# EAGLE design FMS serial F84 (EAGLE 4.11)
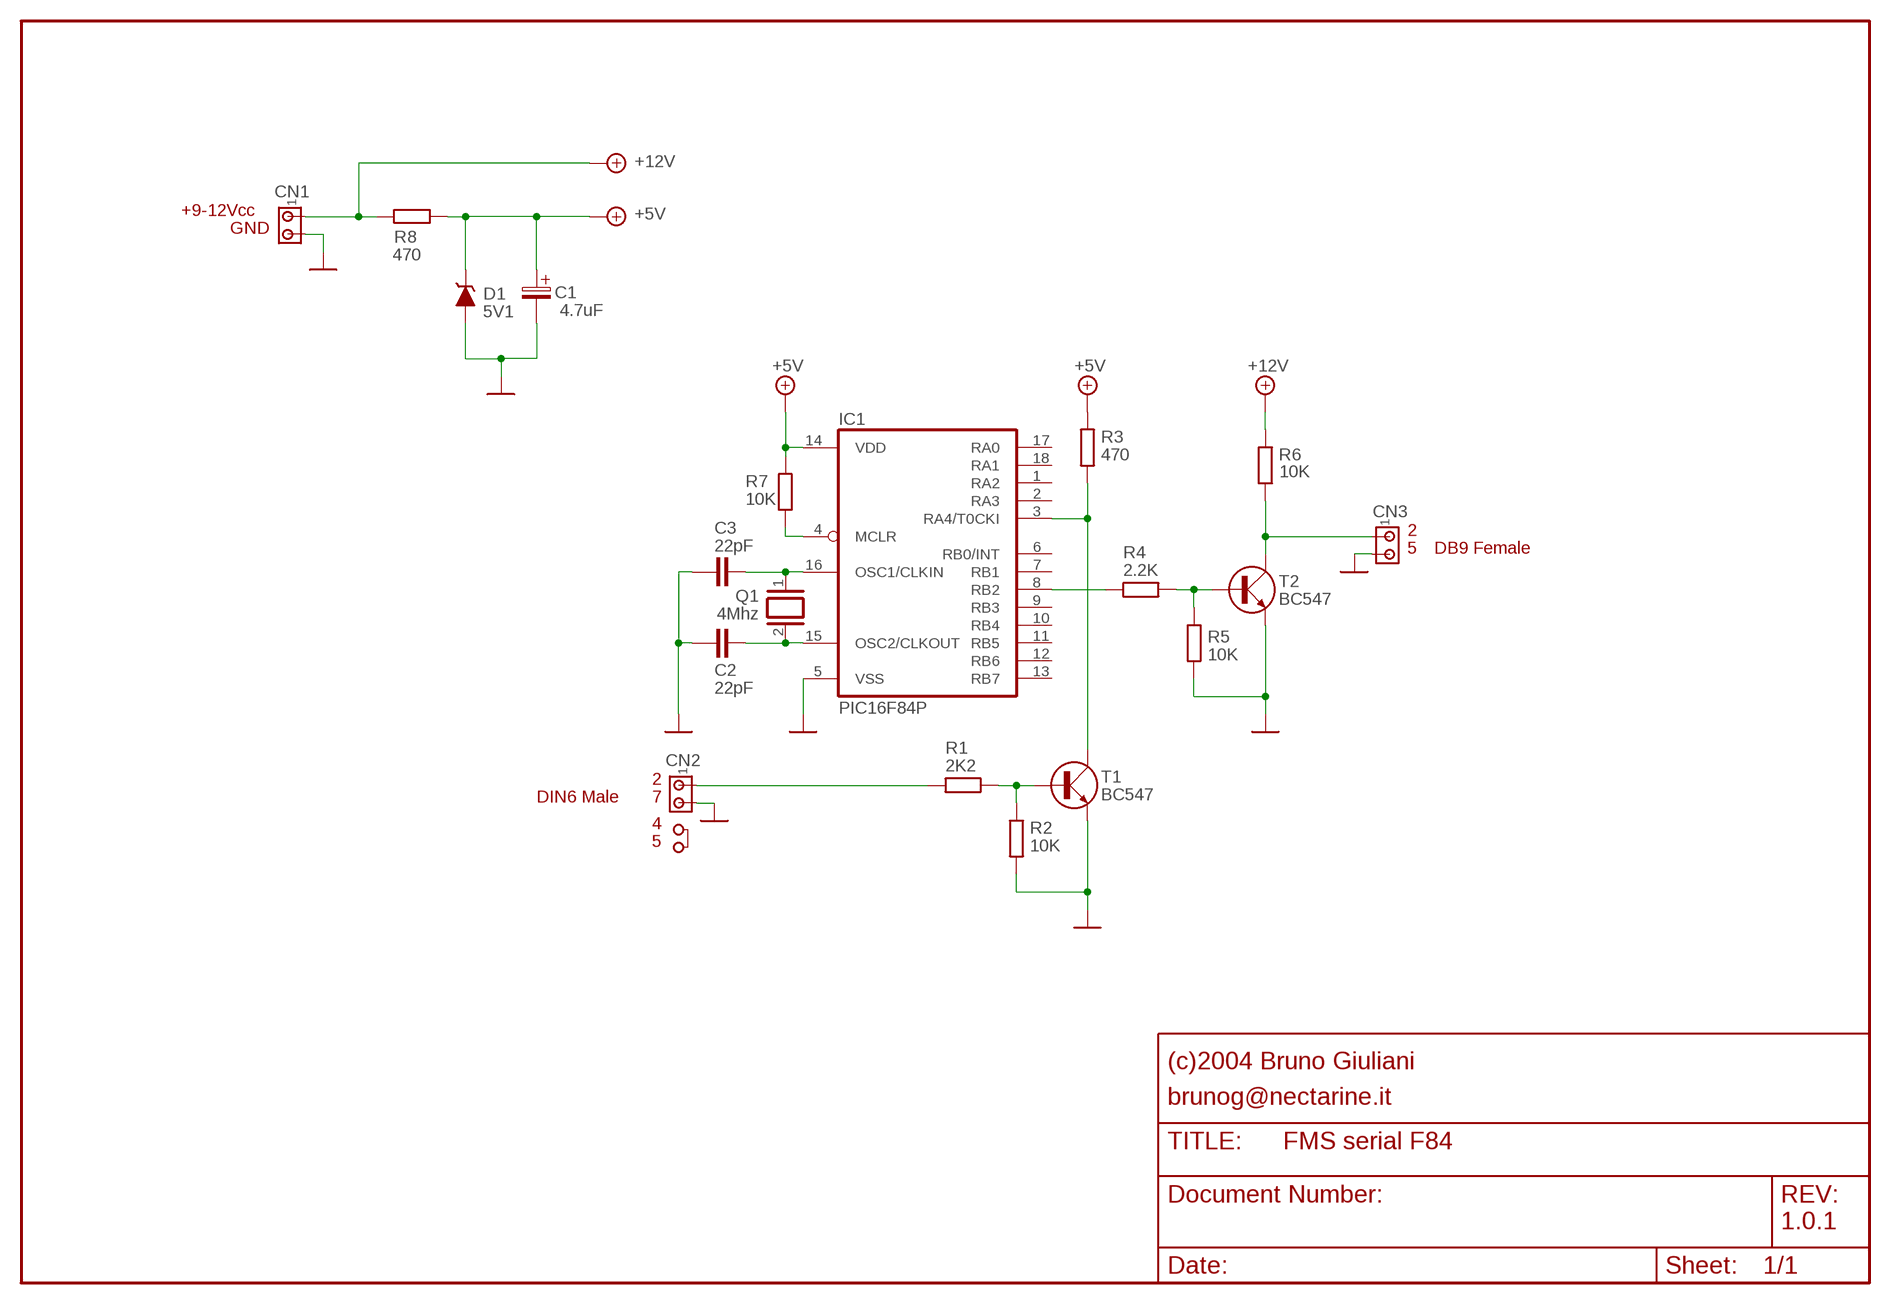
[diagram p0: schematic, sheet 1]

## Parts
C1  4.7uF  ELC2.5  [ES-2.5L]
C2  22pF  C2.5/2  [C2.5-2]
C3  22pF  C2.5/2  [C2.5-2]
CN1  MTA02-100  [10X02MTA]
CN2  MTA02-100  [10X02MTA]
CN3  MTA02-100  [10X02MTA]
D1  5V1  Z  [D-10]
IC1  PIC16F84P  [DIL18]
Q1  4Mhz  XTALS  [QS]
R1  2K2  R  [R-10]
R2  10K  R  [R-10]
R3  470  R  [R-10]
R4  2.2K  R  [R-10]
R5  10K  R  [R-10]
R6  10K  R  [R-10]
R7  10K  R  [R-10]
R8  470  R  [R-10]
T1  BC547  NPN  [TO18]
T2  BC547  NPN  [TO18]

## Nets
+5V: C1.+ D1.C IC1.14(VDD) R3.2 R7.2 R8.1
+12V: CN1.1 R6.2 R8.2
N$1: R1.2 R2.2 T1.B
N$2: IC1.3(RA4/T0CKI) R3.1 T1.C
N$3: R4.2 R5.2 T2.B
N$4: CN2.1 R1.1
N$5: C2.1 IC1.15(OSC2/CLKOUT) Q1.2
N$6: C3.1 IC1.16(OSC1/CLKIN) Q1.1
N$8: C1.- C2.2 C3.2 CN1.2 CN2.2 CN3.2 D1.A IC1.5(VSS) R2.1 R5.1 T1.E T2.E
N$10: IC1.8(RB2) R4.1
N$14: IC1.4(MCLR) R7.1
N$15: CN3.1 R6.1 T2.C
Unconnected: IC1.1(RA2) IC1.2(RA3) IC1.6(RB0/INT) IC1.7(RB1) IC1.9(RB3) IC1.10(RB4) IC1.11(RB5) IC1.12(RB6) IC1.13(RB7) IC1.17(RA0) IC1.18(RA1)

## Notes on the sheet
- +9-12Vcc
- GND
- 2
- 5 | DB9 Female
- 2
- DIN6 Male | 7
- 4
- 5
- (c)2004 Bruno Giuliani
- brunog@nectarine.it
- 1.0.1

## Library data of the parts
C1 = discrete-user:ELC: CAPACITOR
C2 C3 = discrete-user:C: CAPACITOR
CN1-CN3 = con-amp:MTA02-100: AMP connector
D1 = discrete-user:Z: DIODE ZENER
IC1 = PIC16F84:PIC16F84: Microcontroller 8-bit, Flash/EEPROM
Q1 = discrete-user:XTAL: CRYSTAL
R1-R8 = discrete-user:R: RESISTOR
T1 T2 = discrete-user:NPN: NPN TRANSISTOR Created by brugimarcom@supereva.it

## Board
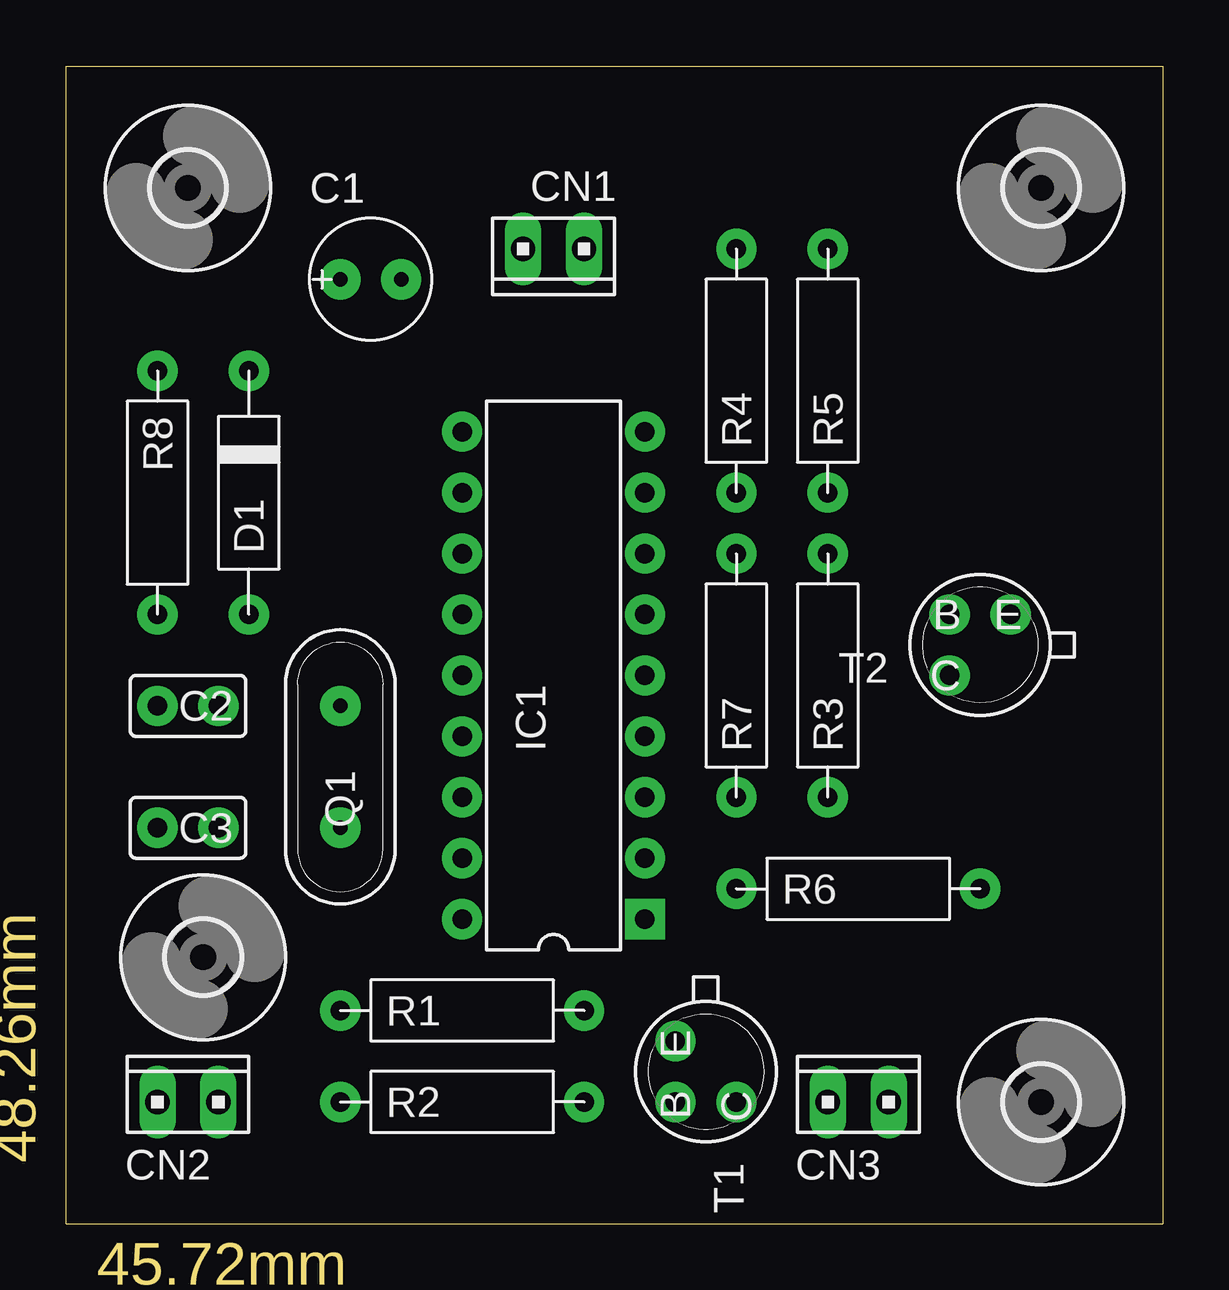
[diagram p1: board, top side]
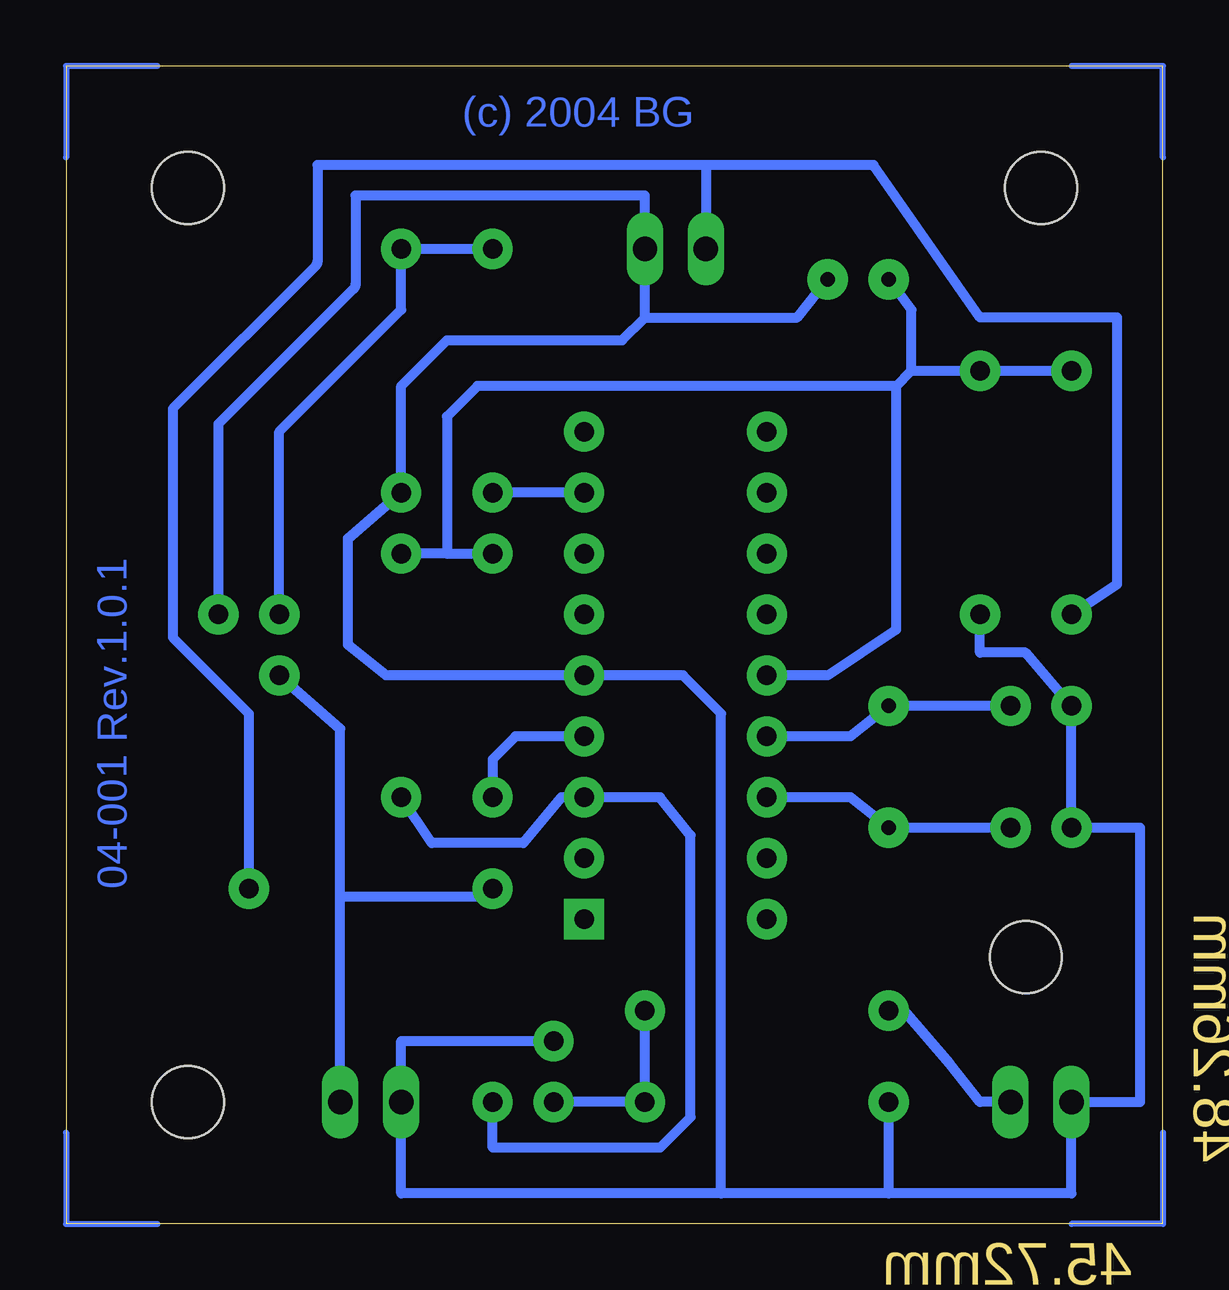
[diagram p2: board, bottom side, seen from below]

Size 45.72 x 48.26 mm. Coordinates in mm from the lower left corner, seen from the top.
Outline: 0,0 45.72,0 45.72,48.26 0,48.26 0,0
Copper layers (1*16): Top 0.035mm / dielectric 1.5mm / Bottom 0.035mm
Design rules "default": minimum track width 10mil, minimum drill 24mil, track to track 8mil, track to pad 8mil, pad to pad 8mil, via to via 8mil, smd to smd 8mil, copper to edge 40mil, drill to drill 8mil, minimum pad ring 10mil, minimum via ring 8mil, stop-mask expansion 4mil, vias tented up to drill 0mil, thermal gap 10mil

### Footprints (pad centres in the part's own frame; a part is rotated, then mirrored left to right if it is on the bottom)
ES-2.5L = drill 0.61 pad 1.676 round: + -1.27,0; - 1.27,0
C2.5-2 = drill 0.813 pad 1.676 round: 1 -1.27,0; 2 1.27,0
10X02MTA = drill 1.016 long: 1 1.27,0; 2 -1.27,0
D-10 = drill 0.813 pad 1.676 round: A -5.08,0; C 5.08,0
DIL18 = drill 0.813 pad 1.676 square: 1 -10.16,-3.81 | drill 0.813 pad 1.676 round: 2 -7.62,-3.81; 3 -5.08,-3.81; 4 -2.54,-3.81; 5 0,-3.81; 6 2.54,-3.81; 7 5.08,-3.81; 8 7.62,-3.81; 9 10.16,-3.81; 10 10.16,3.81; 11 7.62,3.81; 12 5.08,3.81; 13 2.54,3.81; 14 0,3.81; 15 -2.54,3.81; 16 -5.08,3.81; 17 -7.62,3.81; 18 -10.16,3.81
QS = drill 0.61 pad 1.676 round: 1 -2.54,0; 2 2.54,0
R-10 = drill 0.813 pad 1.676 round: 1 -5.08,0; 2 5.08,0
TO18 = drill 0.813 pad 1.676 round: B 1.27,-1.27; C 1.27,1.27; E -1.27,-1.27
3,0 = hole 3: 0,0

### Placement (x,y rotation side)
C1  12.7,39.37 0 top
C2  5.08,21.59 180 top
C3  5.08,16.51 180 top
CN1  20.32,40.64 180 top
CN2  5.08,5.08 0 top
CN3  33.02,5.08 0 top
D1  7.62,30.48 90 top
IC1  20.32,22.86 90 top
Q1  11.43,19.05 90 top
R1  16.51,8.89 0 top
R2  16.51,5.08 0 top
R3  31.75,22.86 90 top
R4  27.94,35.56 90 top
R5  31.75,35.56 90 top
R6  33.02,13.97 0 top
R7  27.94,22.86 90 top
R8  3.81,30.48 270 top
T1  26.67,6.35 270 top
T2  38.1,24.13 180 top
U$1  [3,0]  5.71,11.11 0 top
U$2  [3,0]  40.64,43.18 0 top
U$3  [3,0]  40.64,5.08 0 top
U$4  [3,0]  5.08,43.18 0 top

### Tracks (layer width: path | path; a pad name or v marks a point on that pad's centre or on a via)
+5V
  Bottom 0.406: R8.1 D1.C 10.48,35.56 | 29.84,27.94 R7.2 | 29.84,27.94 R3.2 | 11.11,34.92 11.11,24.77 13.97,22.86 IC1.14 | 29.84,27.94 29.84,33.66 28.57,34.92 11.11,34.92 | 11.11,34.92 10.48,35.56 | 10.48,35.56 10.48,38.1 C1.+
+12V
  Bottom 0.406: 19.05,44.13 12.06,44.13 7.62,37.78 1.91,37.78 1.91,26.67 R8.2 | 19.05,44.13 35.24,44.13 35.24,40.11 arc45 35.32,39.93 41.27,33.97 41.27,24.45 38.1,21.27 R6.2 | 19.05,44.13 CN1.1
N$1
  Bottom 0.406: R1.2 R2.2 T1.B
N$2
  Bottom 0.406: R3.1 30.48,15.88 26.67,15.88 25.08,17.78 IC1.3 20.95,17.78 19.68,16.19 19.68,4.45 20.95,3.17 27.94,3.17 T1.C
N$3
  Bottom 0.406: T2.B 36.83,33.02 31.75,38.1 R5.2 R4.2
N$4
  Bottom 0.406: CN2.1 7.62,5.08 8.89,6.67 10.79,8.89 R1.1
N$5
  Bottom 0.406: C2.1 Q1.2 13.02,20.32 IC1.15
N$6
  Bottom 0.406: C3.1 Q1.1 13.02,17.78 IC1.16
N$7
  Bottom 0.254: 0,3.81 0,0 3.81,0
N$8
  Bottom 0.406: 21.59,37.78 15.24,37.78 C1.- | 21.59,37.78 22.54,36.83 29.84,36.83 31.75,34.92 R5.1 33.97,28.57 33.97,24.13 32.38,22.86 IC1.5 20,22.86 18.41,21.27 18.41,1.27 | 21.59,37.78 CN1.2 21.59,42.86 33.66,42.86 33.66,39.16 arc45 33.73,38.98 39.37,33.34 T2.E | T1.E 31.75,7.62 CN3.2 31.75,1.27 18.41,1.27 | D1.A 7.62,23.81 5.71,23.81 C2.2 C3.2 0.95,16.51 0.95,5.08 CN2.2 3.81,1.27 11.43,1.27 | 11.43,1.27 18.41,1.27 | 11.43,1.27 R2.1
N$9
  Bottom 0.254: 0,44.45 0,48.26 3.81,48.26
N$10
  Bottom 0.406: IC1.8 R4.1
N$11
  Bottom 0.254: 41.91,48.26 45.72,48.26 45.72,44.45
N$12
  Bottom 0.254: 45.72,3.81 45.72,0 41.91,0
N$14
  Bottom 0.406: R7.1 27.94,19.37 26.99,20.32 IC1.4
N$15
  Bottom 0.406: 34.29,13.65 28.57,13.65 R6.1 | CN3.1 34.29,13.65 | 34.29,13.65 34.29,20.64 T2.C

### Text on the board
Bottom: (c) 2004 BG | 04-001 Rev.1.0.1
Dimension: 48.26mm | 45.72mm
